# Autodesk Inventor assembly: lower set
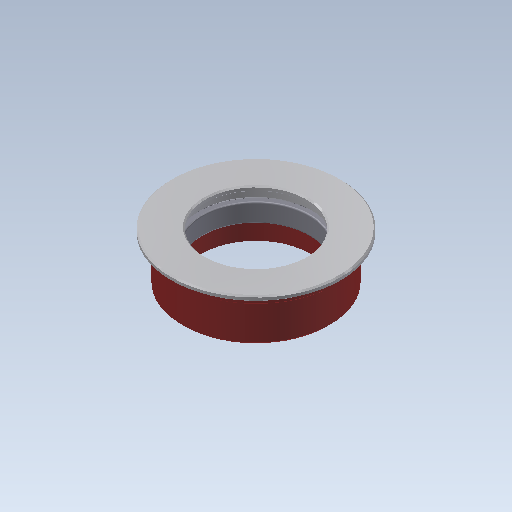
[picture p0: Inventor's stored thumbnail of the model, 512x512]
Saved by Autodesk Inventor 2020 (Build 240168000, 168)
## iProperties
Created: 2017-09
Part Number: lower set
Material: Ogólny
Document SubType Name: Assembly
Designer: Tomasz
Sending System: SolidWorks 2017
Last Author: Tomasz
Last Saved: 2017-09-17
Source: lower set
Author: Tomasz
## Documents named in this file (4)
- C:\Users\bruno\Documents\1-Cours-2020-21\1STI2D-2020-21\IT\6. Antivol\Inventor-Antivol\INVENTOR 2018_Steel Hardtail B+\lower set.iam
- C:\Users\bruno\Documents\1-Cours-2020-21\1STI2D-2020-21\IT\6. Antivol\Inventor-Antivol\INVENTOR 2018_Steel Hardtail B+\Lower cup_1.ipt
- C:\Users\bruno\Documents\1-Cours-2020-21\1STI2D-2020-21\IT\6. Antivol\Inventor-Antivol\INVENTOR 2018_Steel Hardtail B+\Bearing GOST 8338-75 100808.ipt
- C:\Users\bruno\Documents\1-Cours-2020-21\1STI2D-2020-21\IT\6. Antivol\Inventor-Antivol\INVENTOR 2018_Steel Hardtail B+\fork baseplate_1.ipt
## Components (3 placed, 3 different names)
1. Lower cup_1:1
2. Bearing GOST 8338-75 100808:1
3. fork baseplate_1:1
